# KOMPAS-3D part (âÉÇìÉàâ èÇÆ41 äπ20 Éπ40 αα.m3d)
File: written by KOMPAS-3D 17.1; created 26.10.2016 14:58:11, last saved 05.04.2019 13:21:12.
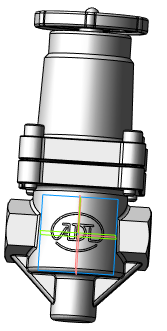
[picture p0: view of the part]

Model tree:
1. Операция без истории:2  (labels: Сталь 20  ГОСТ 1050-88)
